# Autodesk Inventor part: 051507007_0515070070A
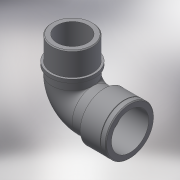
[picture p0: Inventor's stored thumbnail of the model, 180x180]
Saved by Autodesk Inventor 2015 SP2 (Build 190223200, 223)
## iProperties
Created: 2017-05
Part Number: 051507007_0515070070A
Material: Generic
Description: PLASSON 90° THREADED ELBOW MALE-FEMALE 3/4"-3/4"
Document SubType Name: Modeling
Designer: KIM
Mass: 19.9726 g
Surface Area: 123.806 cm^2
Volume: 19.9726 cm^3
Density: 1 g/cm^3
Appearance: Default
Author: KIM
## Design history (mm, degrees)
derived "051507.ipt"
feature "Solid1::051507.ipt"
tag "TaggingFeature1"
body "Solid1"
other parameters: "d2" = 0.5, "d3" = 0.5, "d4" = 31.3521, "d5" = 24.117, "d6" = 18, "d7" = 120 deg, "d8" = 21.6, "d9" = 3.6, "d10" = 26.64929, "d11" = 26.441, "d12" = 17, "d13" = 26.64929, "d14" = 19.83075, "d15" = 19.55, "d16" = 19.83075, "d19" = 0.52882, "d23" = 20.4, "d24" = 29.0851, "d25" = 0, "d26" = 0, "d27" = 18.7, "R_" = 26.441, "Rp_" = 24.117, "l_" = 17, "l_1" = 18
